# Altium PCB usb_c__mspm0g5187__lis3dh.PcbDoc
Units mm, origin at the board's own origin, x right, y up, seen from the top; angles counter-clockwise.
Board outline 92 x 60 mm, 2 copper layers (Top, Bottom), stack 0 mm thick; 34 components, 28 nets, 186 pads, 62 vias.
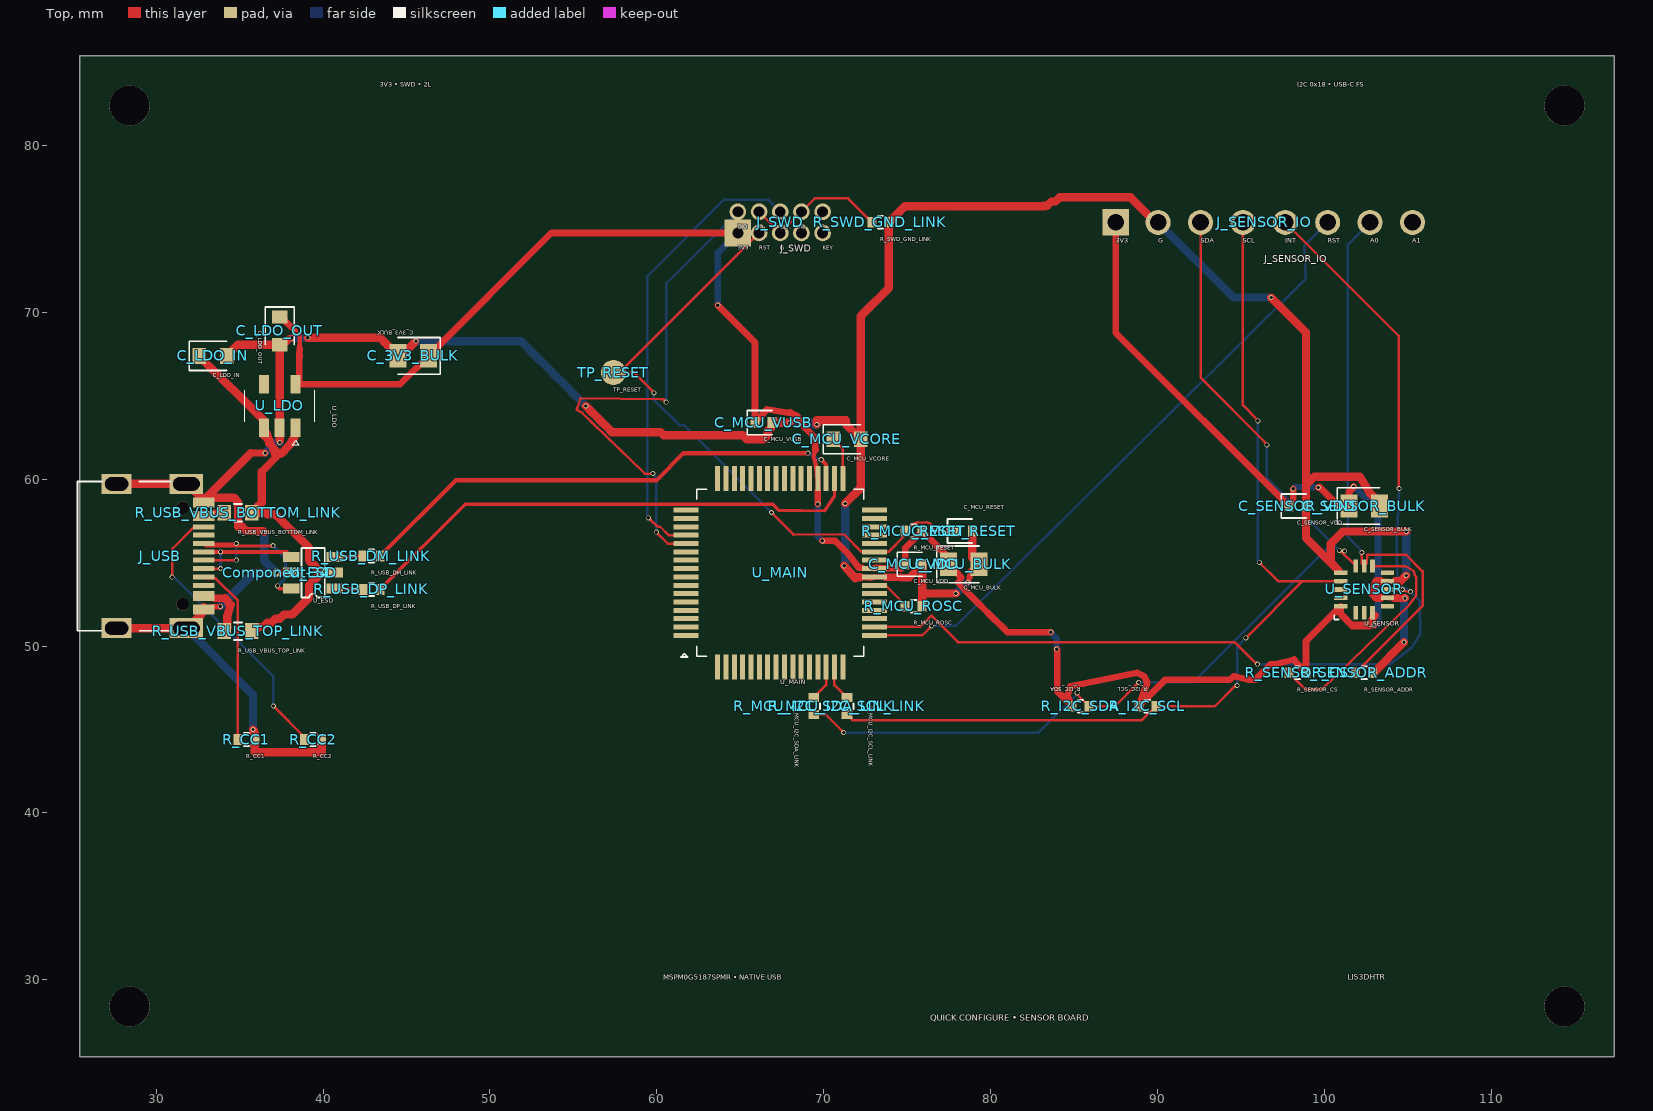
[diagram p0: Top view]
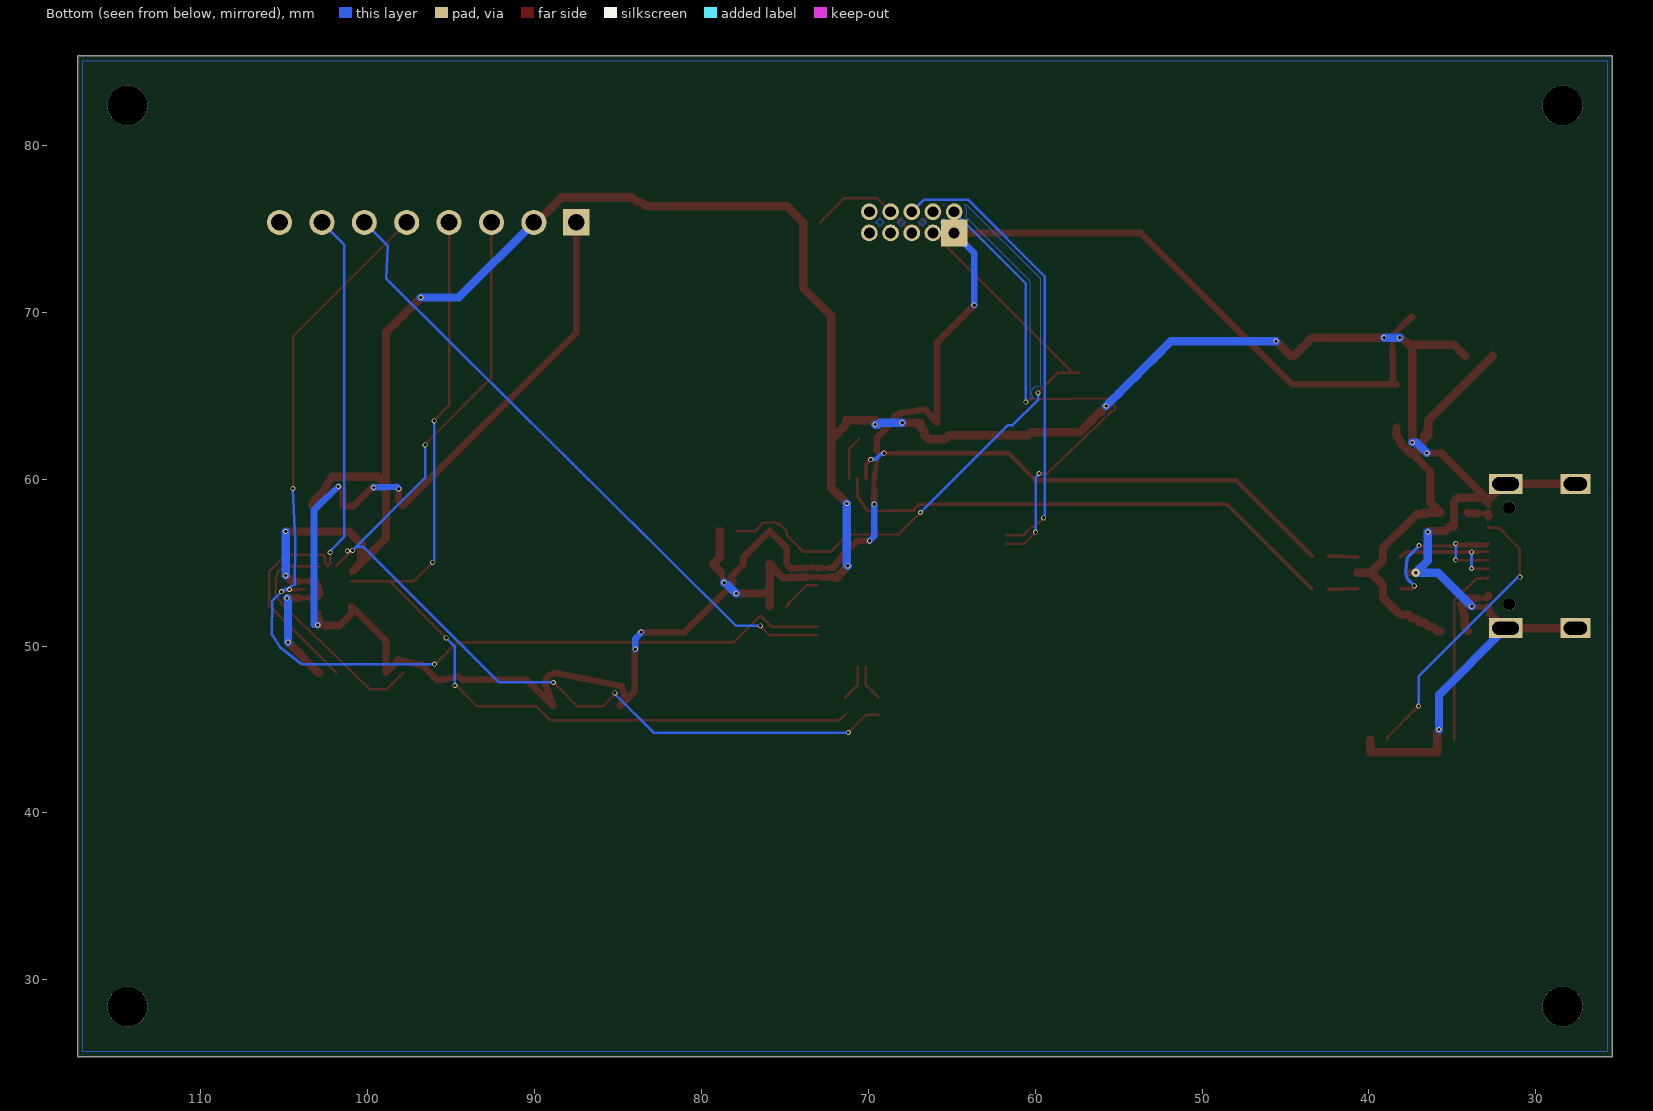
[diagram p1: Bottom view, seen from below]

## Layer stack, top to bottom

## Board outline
25.4,85.4 117.4,85.4 117.4,25.4 25.4,25.4

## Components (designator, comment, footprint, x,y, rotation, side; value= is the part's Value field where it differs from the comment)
C_3V3_BULK "" TSCIRCUIT-2.8500x1.4000mm 45.4,67.4 r180 top
C_LDO_IN "" TSCIRCUIT-2.4500x0.9500mm 33.4,67.4 r0 top
C_LDO_OUT "" TSCIRCUIT-0.9500x2.4500mm 37.4,68.9 r270 top
C_MCU_BULK "" TSCIRCUIT-2.8500x1.4000mm 78.4,54.9 r0 top
C_MCU_RESET "" TSCIRCUIT-1.5600x0.6400mm 78.4,56.9 r0 top
C_MCU_VCORE "" TSCIRCUIT-2.4500x0.9500mm 71.4,62.4 r0 top
C_MCU_VDD "" TSCIRCUIT-1.5600x0.6400mm 75.4,54.9 r0 top
C_MCU_VUSB "" TSCIRCUIT-1.5600x0.6400mm 66.4,63.4 r0 top
C_SENSOR_BULK "" TSCIRCUIT-2.8500x1.4000mm 102.4,58.4 r0 top
C_SENSOR_VDD "" TSCIRCUIT-1.5600x0.6400mm 98.4,58.4 r0 top
Component-34 "" TSCIRCUIT-0.5000x0.5000mm 37.2,54.4 r0 top
J_SENSOR_IO "" TSCIRCUIT-19.2800x1.5000mm 96.4,75.4 r0 top
J_SWD "" TSCIRCUIT-6.0800x2.2700mm 67.4,75.4 r0 top
J_USB "" TSCIRCUIT-6.7732x9.8502mm 30.113,55.4 r90 top
R_CC1 "" TSCIRCUIT-1.5600x0.6400mm 35.4,44.4 r0 top
R_CC2 "" TSCIRCUIT-1.5600x0.6400mm 39.4,44.4 r0 top
R_I2C_SCL "" TSCIRCUIT-1.5600x0.6400mm 89.4,46.4 r180 top
R_I2C_SDA "" TSCIRCUIT-1.5600x0.6400mm 85.4,46.4 r180 top
R_MCU_I2C_SCL_LINK "" TSCIRCUIT-0.6400x1.5600mm 71.4,46.4 r270 top
R_MCU_I2C_SDA_LINK "" TSCIRCUIT-0.6400x1.5600mm 69.4,46.4 r270 top
R_MCU_RESET "" TSCIRCUIT-1.5600x0.6400mm 75.4,56.9 r0 top
R_MCU_ROSC "" TSCIRCUIT-1.5600x0.6400mm 75.4,52.4 r0 top
R_SENSOR_ADDR "" TSCIRCUIT-1.5600x0.6400mm 102.4,48.4 r0 top
R_SENSOR_CS "" TSCIRCUIT-1.5600x0.6400mm 98.4,48.4 r0 top
R_SWD_GND_LINK "" TSCIRCUIT-1.5600x0.6400mm 73.4,75.4 r0 top
R_USB_DM_LINK "" TSCIRCUIT-1.5600x0.6400mm 42.9,55.4 r0 top
R_USB_DP_LINK "" TSCIRCUIT-1.5600x0.6400mm 42.9,53.4 r0 top
R_USB_VBUS_BOTTOM_LINK "" TSCIRCUIT-2.4500x0.9500mm 34.9,58 r0 top
R_USB_VBUS_TOP_LINK "" TSCIRCUIT-2.4500x0.9500mm 34.9,50.9 r0 top
TP_RESET "" TSCIRCUIT-1.5000x1.5000mm 57.4,66.4 r0 top
U_ESD "" TSCIRCUIT-3.6000x2.5000mm 39.4,54.4 r0 top
U_LDO "" TSCIRCUIT-2.5000x3.7000mm 37.4,64.4 r270 top
U_MAIN "" TSCIRCUIT-12.8000x12.8000mm 67.4,54.4 r0 top
U_SENSOR "" TSCIRCUIT-3.6001x3.5998mm 102.4,53.4 r0 top

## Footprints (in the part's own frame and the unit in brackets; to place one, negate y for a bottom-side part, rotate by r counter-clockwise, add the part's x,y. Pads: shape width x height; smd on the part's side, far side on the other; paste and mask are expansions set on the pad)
TSCIRCUIT-0.5000x0.5000mm [mm]
TSCIRCUIT-0.6400x1.5600mm [mm]
  rect 0.54x0.64 smd: 1(-0.51,0) 2(0.51,0)
  silkscreen extent -0.15,-0.38 0.15,0.38
TSCIRCUIT-0.9500x2.4500mm [mm]
  rect 0.8x0.95 smd: 1(-0.825,0) 2(0.825,0)
  silkscreen extent -1.43,-0.87 0.82,0.88
TSCIRCUIT-1.5000x1.5000mm [mm]
  round 1.5 smd: 1(0,0)
TSCIRCUIT-1.5600x0.6400mm [mm]
  rect 0.54x0.64 smd: 1(-0.51,0) 2(0.51,0)
  silkscreen extent -0.98,-0.72 0.51,0.72
TSCIRCUIT-2.4500x0.9500mm [mm]
  rect 0.8x0.95 smd: 1(-0.825,0) 2(0.825,0)
  silkscreen extent -1.42,-0.87 0.82,0.87
TSCIRCUIT-2.5000x3.7000mm [mm]
  rect 1.1x0.6 smd: 1(1.3,0.95) 2(1.3,0) 3(1.3,-0.95) 4(-1.3,-0.95) 5(-1.3,0.95)
  silkscreen extent -0.95,-2.1 2.35,2.1
TSCIRCUIT-2.8500x1.4000mm [mm]
  rect 1.025x1.4 smd: 1(-0.913,0) 2(0.913,0)
  silkscreen extent -1.63,-1.1 0.91,1.1
TSCIRCUIT-3.6000x2.5000mm [mm]
  rect 1x0.6 smd: 1(-1.3,-0.95) 2(-1.3,0) 3(-1.3,0.95) 4(1.3,0.95) 5(1.3,0) 6(1.3,-0.95)
  silkscreen extent -0.7,-1.49 0.7,1.49
TSCIRCUIT-3.6001x3.5998mm [mm]
  rect 0.8x0.28 smd: 1(-1.4,-1) 2(-1.4,-0.5) 3(-1.4,0) 4(-1.4,0.5) 5(-1.4,1) 9(1.4,1) 10(1.4,0.5) 11(1.4,0) 12(1.4,-0.5) 13(1.4,-1)
  rect 0.28x0.8 smd: 6(-0.5,1.4) 7(0,1.4) 8(0.5,1.4) 14(0.5,-1.4) 15(0,-1.4) 16(-0.5,-1.4)
  silkscreen extent -1.8,-1.8 -1.52,-1.52
TSCIRCUIT-6.0800x2.2700mm [mm]
  rect 1.6x1.6 hole 0.65: 1(-2.54,-0.635)
  round 1 hole 0.65: 2(-2.54,0.635) 3(-1.27,0.635) 4(0,0.635) 5(1.27,0.635) 6(2.54,0.635) 7(2.54,-0.635) 8(1.27,-0.635) 9(0,-0.635) 10(-1.27,-0.635)
TSCIRCUIT-6.7732x9.8502mm [mm]
  rect 0.3x1.3 smd: 1(-3.35,-2.737) 2(-3.05,-2.737) 3(-2.55,-2.737) 4(-2.25,-2.737) 5(-1.75,-2.737) 6(-1.25,-2.737) 7(-0.75,-2.737) 8(-0.25,-2.737) 9(0.25,-2.737) 10(0.75,-2.737) 11(1.25,-2.737) 12(1.75,-2.737) 13(2.55,-2.737) 14(2.25,-2.737) 15(3.35,-2.737) 16(3.05,-2.737)
  rect 1.2x2 hole 0.8 slot 1.6 at 90 deg: 17(-4.325,-1.693) 18(4.325,-1.693)
  rect 1.2x1.8 hole 0.8 slot 1.4 at 90 deg: 19(4.325,2.487) 20(-4.325,2.487)
  round 0.75 hole 0.75 unplated: NPTH-1(-2.9,-1.468) NPTH-2(2.9,-1.468)
  silkscreen extent -4.47,-0.75 4.47,4.83
TSCIRCUIT-12.8000x12.8000mm [mm]
  rect 1.5x0.3 smd: 1(-5.65,-3.75) 2(-5.65,-3.25) 3(-5.65,-2.75) 4(-5.65,-2.25) 5(-5.65,-1.75) 6(-5.65,-1.25) 7(-5.65,-0.75) 8(-5.65,-0.25) 9(-5.65,0.25) 10(-5.65,0.75) 11(-5.65,1.25) 12(-5.65,1.75) 13(-5.65,2.25) 14(-5.65,2.75) 15(-5.65,3.25) 16(-5.65,3.75) 33(5.65,3.75) 34(5.65,3.25) 35(5.65,2.75) 36(5.65,2.25) 37(5.65,1.75) 38(5.65,1.25) 39(5.65,0.75) 40(5.65,0.25) 41(5.65,-0.25) 42(5.65,-0.75) 43(5.65,-1.25) 44(5.65,-1.75) 45(5.65,-2.25) 46(5.65,-2.75) 47(5.65,-3.25) 48(5.65,-3.75)
  rect 0.3x1.5 smd: 17(-3.75,5.65) 18(-3.25,5.65) 19(-2.75,5.65) 20(-2.25,5.65) 21(-1.75,5.65) 22(-1.25,5.65) 23(-0.75,5.65) 24(-0.25,5.65) 25(0.25,5.65) 26(0.75,5.65) 27(1.25,5.65) 28(1.75,5.65) 29(2.25,5.65) 30(2.75,5.65) 31(3.25,5.65) 32(3.75,5.65) 49(3.75,-5.65) 50(3.25,-5.65) 51(2.75,-5.65) 52(2.25,-5.65) 53(1.75,-5.65) 54(1.25,-5.65) 55(0.75,-5.65) 56(0.25,-5.65) 57(-0.25,-5.65) 58(-0.75,-5.65) 59(-1.25,-5.65) 60(-1.75,-5.65) 61(-2.25,-5.65) 62(-2.75,-5.65) 63(-3.25,-5.65) 64(-3.75,-5.65)
  silkscreen extent -5.95,-5.05 5,5
TSCIRCUIT-19.2800x1.5000mm [mm]
  rect 1.6x1.6 hole 1: 1(-8.89,0)
  round 1.5 hole 1: 2(-6.35,0) 3(-3.81,0) 4(-1.27,0) 5(1.27,0) 6(3.81,0) 7(6.35,0) 8(8.89,0)

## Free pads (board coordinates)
  round 2.4 hole 2.4 unplated: NPTH-3(28.4,28.4) NPTH-4(114.4,28.4) NPTH-5(28.4,82.4) NPTH-6(114.4,82.4)

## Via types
v1: diameter 0.3, hole 0.2, Top to Bottom, 61 vias
v2: diameter 0.5, hole 0.2, Top to Bottom, 1 vias

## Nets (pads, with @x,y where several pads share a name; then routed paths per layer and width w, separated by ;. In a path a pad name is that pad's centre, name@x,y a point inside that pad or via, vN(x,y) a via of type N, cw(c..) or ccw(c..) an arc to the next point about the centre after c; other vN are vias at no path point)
".J_SWD > .pin2 to .U_MAIN > .pin12": J_SWD.2 U_MAIN.12 | length 30.9
  Top w0.15: v1(59.764,60.346) 59.277,60.346 56.137,63.368 55.527,63.99 55.2,64.175 55.425,64.85 60.238,64.787 60.405,64.787 v1(60.566,64.626) ; v1(59.968,56.831) 60.016,56.791 60.657,56.15 U_MAIN.12
  Bottom w0.15: v1(59.764,60.346) 59.801,60.301 59.801,60.266 59.97,60.097 v1(59.968,56.831) ; v1(60.566,64.626) 60.566,71.741 J_SWD.2
".J_SWD > .pin4 to .U_MAIN > .pin13": J_SWD.4 U_MAIN.13 | length 27.3
  Top w0.15: v1(59.492,57.694) 59.614,57.572 59.632,57.572 60.051,57.161 60.209,57.155 60.714,56.65 U_MAIN.13
  Bottom w0.15: v1(59.492,57.694) 59.423,57.756 59.428,72.167 64.005,76.742 66.693,76.742 J_SWD.4
".U_MAIN > .pin42 to .R_MCU_ROSC > .pin1": R_MCU_ROSC.1 U_MAIN.42 | length 2.4
  Top w0.15: U_MAIN.42 73.719,53.65 74.769,52.6 74.769,52.521 R_MCU_ROSC.1
GND: C_3V3_BULK.2 C_LDO_IN.2 C_LDO_OUT.2 C_MCU_BULK.2 C_MCU_RESET.2 C_MCU_VCORE.2 C_MCU_VDD.2 C_MCU_VUSB.2 C_SENSOR_BULK.2 C_SENSOR_VDD.2 J_SENSOR_IO.2 J_USB.1 J_USB.2 J_USB.15 J_USB.16 J_USB.17 J_USB.18 J_USB.19 J_USB.20 R_CC1.2 R_CC2.2 R_MCU_ROSC.2 R_SENSOR_ADDR.2 R_SWD_GND_LINK.2 U_ESD.2 U_LDO.2 U_MAIN.41 U_SENSOR.5 U_SENSOR.10 U_SENSOR.12 | length 203.3
  Top w0.275: J_USB.16 J_USB.15@33.04,58.641
  Top w0.28: U_SENSOR.12@103.4,52.9 U_SENSOR.12 ; U_SENSOR.10@103.4,53.9 U_SENSOR.10 103.894,53.9 103.988,53.9 104.081,53.9 104.175,53.9 104.2,53.9 104.269,53.9 ; U_SENSOR.5@100.86,54.54 U_SENSOR.5 U_SENSOR.5@100.86,54.54
  Top w0.287: U_SENSOR.12 103.817,52.883 104.159,52.88 U_SENSOR.12@104.2,52.88
  Top w0.3: J_USB.1@32.699,51.9 J_USB.1 J_USB.1@32.849,52.2 ; J_USB.15@32.699,58.9 J_USB.15 ; J_USB.16@32.849,58.6 J_USB.15 ; J_USB.15@32.999,58.9 J_USB.15 ; J_USB.15@33.04,58.641 33.231,58.832 33.332,58.832 33.4,58.9 33.499,58.9 ; U_MAIN.41 73.144,54.15 73.237,54.15 73.331,54.15 73.425,54.15 73.519,54.15 73.612,54.15 U_MAIN.41@73.706,54.15
  Top w0.325: J_USB.2 J_USB.2@32.887,52.324 ; J_USB.16 J_USB.16@32.849,58.6 ; v1(37.395,62.205) v1@37.4,62.35 ; v1(78.645,53.806) 78.741,54.116
  Top w0.33: U_MAIN.41@72.425,54.117 72.55,54.114 U_MAIN.41@72.675,54.112
  Top w0.331: U_MAIN.41@72.675,54.112 U_MAIN.41@72.796,54.101
  Top w0.335: 72.3,54.12 U_MAIN.41@72.425,54.117
  Top w0.35: J_USB.2@32.887,52.324 33.362,52.354 v1(33.836,52.384) ; 37.968,68.441 38.124,68.441 v1(38.153,68.477)
  Top w0.375: 45.429,68.145 45.435,68.145 v1(45.568,68.278) ; U_MAIN.41@72.796,54.101 U_MAIN.41 ; 78.741,54.116 C_MCU_BULK.2@78.838,54.425
  Top w0.4: 35.673,61.574 36.1,61.574 v1(36.527,61.574) ; 37.2,54.4 U_ESD.2@37.6,54.4 ; 72.175,54.12 72.3,54.12
  Top w0.425: C_LDO_OUT.2@37.785,68.258 37.968,68.441
  Top w0.437: 75.119,54.087 75.337,54.306 75.556,54.525
  Top w0.45: 74.648,54.108 75.119,54.087
  Top w0.475: U_MAIN.41@73.706,54.15 74.177,54.129 74.648,54.108 ; 104.2,52.88 104.501,52.877 v1(104.844,52.874)
  Top w0.5: J_USB.20 J_USB.17 31.874,51.075 32.474,51.675 32.699,51.9 ; J_USB.19 J_USB.18 31.874,59.725 32.474,59.125 32.699,58.9 ; J_USB.1@32.849,52.2 J_USB.2 ; 32.999,58.9 35.673,61.574 ; 33.499,58.9 34.65,58.9 34.9,58.65 34.9,57.15 35.15,57.15 35.4,56.9 36.409,56.9 v1(36.463,56.846) ; C_LDO_IN.2 34.9,68.075 C_LDO_OUT.2 ; v1(35.8,45) 35.838,44.962 35.838,44.87 35.91,44.798 R_CC1.2 35.91,43.65 39.91,43.65 R_CC2.2 ; v1@37.4,62.35 37.4,62.725 U_LDO.2 C_LDO_OUT.2 ; C_LDO_OUT.2@37.785,68.258 37.603,68.075 C_LDO_OUT.2 ; v1(39.081,68.491) 39.56,68.491 40.04,68.491 40.519,68.491 40.999,68.491 41.478,68.491 41.958,68.491 42.437,68.491 42.917,68.491 43.396,68.491 43.669,68.218 43.942,67.946 44.215,67.673 C_3V3_BULK.2 44.683,67.4 44.932,67.648 45.18,67.897 45.429,68.145 ; v1(55.747,64.394) 56.062,64.079 56.376,63.765 56.691,63.45 57.005,63.136 57.32,62.821 57.794,62.821 58.268,62.821 58.743,62.821 59.217,62.821 59.691,62.821 60.166,62.821 60.229,62.821 60.4,62.65 65.15,62.65 65.4,62.4 66.4,62.4 66.65,62.65 66.65,62.9 66.9,63.15 66.9,63.4 C_MCU_VUSB.2 67.91,63.4 v1(67.97,63.39) ; v1(69.589,63.289) 69.589,63.539 71.336,63.539 71.336,63.289 C_MCU_VCORE.2 ; v1(71.229,54.813) 71.898,54.077 72.05,54.12 72.175,54.12 ; v1(71.292,58.547) 72.225,59.48 C_MCU_VCORE.2 ; 75.556,54.525 75.66,54.65 C_MCU_VDD.2 ; R_MCU_ROSC.2 C_MCU_VDD.2 ; v1(77.92,53.159) 75.91,53.159 C_MCU_VDD.2 ; C_MCU_BULK.2@78.838,54.425 79.075,54.662 C_MCU_BULK.2 78.91,55.303 C_MCU_RESET.2 ; J_SENSOR_IO.2 89.9,75.4 88.4,76.9 84.15,76.9 83.9,76.65 83.65,76.65 83.4,76.4 83.202,76.4 83.235,76.366 82.748,76.366 82.261,76.366 81.773,76.366 81.286,76.366 80.799,76.366 80.311,76.366 79.824,76.366 79.337,76.366 78.849,76.366 78.362,76.366 77.875,76.366 77.387,76.366 76.9,76.366 76.413,76.366 75.925,76.366 75.438,76.366 74.951,76.366 74.876,76.366 74.554,76.044 74.232,75.722 R_SWD_GND_LINK.2 73.91,71.464 72.225,69.779 72.225,69.287 72.225,68.795 72.225,68.303 72.225,67.812 72.225,67.32 72.225,66.828 72.225,66.336 72.225,65.844 72.225,65.352 72.225,64.86 72.225,64.368 72.225,63.876 72.225,63.384 72.225,62.892 C_MCU_VCORE.2 ; v1(96.819,70.897) 98.91,68.806 C_SENSOR_VDD.2 ; R_SENSOR_ADDR.2 102.947,48.4 v1(104.788,50.24) ; C_SENSOR_BULK.2 103.318,58.573 103.029,58.873 102.74,59.173 102.15,60.15 99.4,60.15 98.91,59.66 C_SENSOR_VDD.2 ; U_SENSOR.12@103.4,52.9 103.15,52.9 102.9,53.15 103.15,53.9 U_SENSOR.10@103.4,53.9 ; 104.269,53.9 104.363,53.9 104.456,53.9 104.55,53.9 104.579,53.9 104.912,54.233 v1(104.915,54.236) ; v1(104.925,56.871) 101.121,56.871 100.4,56.15 100.4,55 100.86,54.54 98.91,56.49 C_SENSOR_VDD.2
  Bottom w0.5: J_USB.17 35.8,47.081 v1(35.8,45) ; v1(33.836,52.384) 35.853,54.4 37.2,54.4 36.954,54.646 36.709,54.891 36.463,55.137 36.463,55.564 36.463,55.992 36.463,56.419 v1(36.463,56.846) ; v1(36.527,61.574) 37.158,62.205 v1(37.395,62.205) ; v1(38.153,68.477) 39.067,68.477 v1(39.081,68.491) ; v1(45.568,68.278) 46.052,68.278 46.536,68.278 47.021,68.278 47.505,68.278 47.989,68.278 48.473,68.278 48.958,68.278 49.442,68.278 49.926,68.278 50.41,68.278 50.895,68.278 51.379,68.278 51.863,68.278 52.214,67.927 52.564,67.577 52.915,67.226 53.265,66.876 53.616,66.525 53.966,66.175 54.317,65.824 54.667,65.474 55.018,65.123 55.368,64.773 55.719,64.422 v1(55.747,64.394) ; v1(67.97,63.39) 69.286,63.4 69.422,63.263 69.563,63.263 v1(69.589,63.289) ; v1(71.229,54.813) 71.292,54.876 v1(71.292,58.547) ; v1(77.92,53.159) 77.939,53.159 78.197,53.417 78.455,53.675 78.475,53.675 v1(78.645,53.806) ; J_SENSOR_IO.2 94.553,70.897 v1(96.819,70.897) ; v1(104.788,50.24) 104.788,52.818 v1(104.844,52.874) ; v1(104.915,54.236) 104.915,56.861 v1(104.925,56.871)
MAIN_RESET: C_MCU_RESET.1 J_SWD.10 R_MCU_RESET.1 TP_RESET.1 U_MAIN.38 | length 38.6
  Top w0.15: v1(59.83,65.183) 59.715,65.298 59.715,65.315 58.629,66.4 TP_RESET.1 57.765,66.4 J_SWD.10 ; v1(66.872,58.008) 68.193,56.687 70.959,56.71 71.235,56.687 72.273,55.65 U_MAIN.38 73.889,55.65 74.889,56.651 R_MCU_RESET.1@74.889,56.899 ; R_MCU_RESET.1 75.256,57.266 75.34,57.266 75.254,57.273 75.637,57.423 75.9,57.41 76.161,57.425 76.332,57.372 76.764,56.9 C_MCU_RESET.1
  Bottom w0.15: v1(59.83,65.183) 59.83,64.765 61.351,63.244 61.636,63.244 66.85,58.03 v1(66.872,58.008)
MCU_I2C_SCL_LOCAL: R_MCU_I2C_SCL_LINK.1 U_MAIN.50 | length 2.2
  Top w0.15: U_MAIN.50 70.65,47.66 R_MCU_I2C_SCL_LINK.1
MCU_I2C_SDA_LOCAL: R_MCU_I2C_SDA_LINK.1 U_MAIN.51 | length 2.2
  Top w0.15: R_MCU_I2C_SDA_LINK.1 70.15,47.66 U_MAIN.51
MSPM0_VCORE: C_MCU_VCORE.1 U_MAIN.32 | length 2.6
  Top w0.15: C_MCU_VCORE.1 71.15,61.825 U_MAIN.32
SENSOR_ADDR0: J_SENSOR_IO.7 R_SENSOR_ADDR.1 U_SENSOR.7 | length 33.8
  Top w0.15: R_SENSOR_ADDR.1 105.906,52.416 105.906,54.486 104.917,55.476 102.577,55.476 102.564,54.982 U_SENSOR.7 102.254,54.946 v1(102.254,55.615)
  Bottom w0.15: v1(102.254,55.615) 102.194,55.675 102.194,55.775 101.417,56.552 101.417,56.703 101.417,74.067 J_SENSOR_IO.7
SENSOR_ADDR1: J_SENSOR_IO.8
SENSOR_CS: R_SENSOR_CS.1 U_SENSOR.8 | length 14.4
  Top w0.15: R_SENSOR_CS.1 98.885,47.405 99.859,47.404 105.103,52.473 105.524,53.055 105.515,54.154 105.421,54.247 105.375,54.5 104.869,54.8 U_SENSOR.8
SENSOR_INT: J_SENSOR_IO.5 U_MAIN.47 U_SENSOR.11 | length 66
  Top w0.15: U_MAIN.47 75.785,51.15 76.46,51.825 78.046,50.238 94.621,50.238 94.631,50.238 95.861,49.009 95.915,49.009 v1(96.005,48.919) ; J_SENSOR_IO.5 104.471,68.599 104.471,59.467 104.475,59.467 v1(104.497,59.445) ; v1(104.7,53.4) U_SENSOR.11 v1(105.179,53.265)
  Bottom w0.15: v1(96.005,48.919) 103.957,48.914 105.235,49.903 105.745,50.698 105.738,52.706 105.22,53.224 v1(105.179,53.265) ; v1(104.497,59.445) 104.365,56.306 104.368,53.673 105.205,53.315 105.205,53.291 v1(104.7,53.4)
SENSOR_RESET: J_SENSOR_IO.6 U_MAIN.48 | length 38.6
  Top w0.15: U_MAIN.48 75.912,50.65 76.363,51.101 76.363,51.109 v1(76.476,51.222)
  Bottom w0.15: v1(76.476,51.222) 77.919,51.214 98.889,72.017 98.798,73.988 J_SENSOR_IO.6
SENSOR_SCL: J_SENSOR_IO.4 R_I2C_SCL.1 R_MCU_I2C_SCL_LINK.2 U_SENSOR.4 | length 60.7
  Top w0.15: R_MCU_I2C_SCL_LINK.2 71.719,45.571 89.004,45.571 89.081,45.571 R_I2C_SCL.1 93.449,46.4 94.659,47.61 94.745,47.61 v1(94.781,47.646) ; J_SENSOR_IO.4 95.13,64.445 96.045,63.529 96.045,63.525 v1(96.02,63.5) ; v1(95.31,50.501) 98.709,53.9 U_SENSOR.4 97.234,53.9 v1(96.11,55.024)
  Bottom w0.15: v1(94.781,47.646) 94.781,49.962 95.264,50.444 95.264,50.455 v1(95.31,50.501) ; v1(96.02,63.5) 96.02,55.126 96.108,55.038 96.108,55.026 v1(96.11,55.024)
SENSOR_SDA: J_SENSOR_IO.3 R_I2C_SDA.1 R_MCU_I2C_SDA_LINK.2 U_SENSOR.6 | length 63.9
  Top w0.15: R_MCU_I2C_SDA_LINK.2 70.13,45.89 71.028,44.992 v1(71.2,44.82) ; v1(85.2,47.2) 85.2,47.11 R_I2C_SDA.1 87.457,46.4 88.818,47.761 v1(88.882,47.825) ; J_SENSOR_IO.3 92.59,66.096 96.441,62.245 96.441,62.184 v1(96.56,62.065) ; v1(100.914,55.745) v1@100.955,55.745 ; v1(101.225,55.7) v1@100.955,55.745 ; v1@100.955,55.745 U_SENSOR.6 v1@100.955,55.745
  Bottom w0.15: v1(71.2,44.82) 82.879,44.82 85.2,47.141 v1(85.2,47.2) ; v1(88.882,47.825) 92.146,47.825 100.267,55.946 100.665,55.946 100.913,55.698 100.913,55.744 v1(101.225,55.7) ; v1(96.56,62.065) 96.56,60.1 v1@100.831,55.829 ; v1@100.831,55.828 v1(100.914,55.745)
swd-ground-1-to-2: J_SWD.3 J_SWD.5 J_SWD.9 R_SWD_GND_LINK.1 | length 8.8
  Top w0.15: J_SWD.3 J_SWD.9 J_SWD.5 69.481,76.846 71.471,76.846 71.471,76.819 R_SWD_GND_LINK.1
usb-dm-device: R_USB_DM_LINK.1 U_ESD.4 | length 1.7
  Top w0.25: U_ESD.4 R_USB_DM_LINK.1
usb-dm-mcu: R_USB_DM_LINK.2 U_MAIN.30 | length 30.4
  Top w0.25: R_USB_DM_LINK.2 47.95,59.94 59.983,59.94 61.609,61.566 v1(69.057,61.566) ; v1(69.857,61.178) 70.15,60.885 U_MAIN.30
  Bottom w0.25: v1(69.057,61.566) 69.107,61.516 69.248,61.516 69.585,61.178 v1(69.857,61.178)
usb-dm-port-tie: J_USB.7 J_USB.9 U_ESD.3 | length 8.4
  Top w0.15: J_USB.7 v1(33.85,54.65) ; J_USB.9@33.35,55.65 33.318,55.65 33.224,55.65 33.13,55.65 33.037,55.65 32.943,55.65 J_USB.9 v1(33.85,55.65)
  Top w0.175: J_USB.9@33.35,55.65 J_USB.9@33.412,55.65
  Top w0.212: J_USB.9@33.412,55.65 33.505,55.65
  Top w0.25: 33.505,55.65 33.599,55.645 37.8,55.631 U_ESD.3
  Bottom w0.15: v1(33.85,54.65) v1(33.85,55.65)
usb-dp-device: R_USB_DP_LINK.1 U_ESD.6 | length 1.7
  Top w0.25: U_ESD.6 R_USB_DP_LINK.1
usb-dp-mcu: R_USB_DP_LINK.2 U_MAIN.31 | length 31
  Top w0.2: R_USB_DP_LINK.2 48.512,58.502 48.527,58.502 66.966,58.502 67.008,58.46 67.319,58.148 70.05,58.1 70.65,58.99 U_MAIN.31
usb-dp-port-tie: J_USB.8 J_USB.10 U_ESD.1 | length 12.9
  Top w0.15: J_USB.8 v1(34.8,55.15) ; J_USB.10 v1(34.8,56.15)
  Top w0.2: J_USB.10 32.999,56 v1(37,56.024) ; v1(37.275,53.615) 37.358,53.532 37.358,53.47 37.379,53.45 U_ESD.1
  Bottom w0.15: v1(34.8,55.15) v1(34.8,56.15)
  Bottom w0.2: v1(37,56.024) 37.079,55.921 37.71,55.289 37.71,55.183 37.8,54.5 37.71,54.05 v1(37.275,53.615)
USB_CC1: J_USB.6 R_CC1.1 | length 11
  Top w0.15: J_USB.6 32.937,54.062 33.562,54.062 34.89,52.734 R_CC1.1
USB_CC2: J_USB.12 R_CC2.1 | length 17.2
  Top w0.15: v1(30.956,54.138) 30.956,55.826 32.236,57.106 32.805,57.106 J_USB.12 ; v1(37.019,46.41) 37.075,46.354 38.89,44.539 R_CC2.1
  Bottom w0.15: v1(30.956,54.138) 31.061,54.138 37.019,48.18 v1(37.019,46.41)
USB_VBUS_BOTTOM_LOCAL: J_USB.13 J_USB.14 R_USB_VBUS_BOTTOM_LINK.1 | length 1.5
  Top w0.3: J_USB.14 J_USB.14@32.849,57.8 ; J_USB.13 32.927,57.95 33.005,57.95 33.083,57.95 33.161,57.95 33.239,57.95 33.317,57.95 33.394,57.95 33.472,57.95 33.499,57.95
  Top w0.475: J_USB.13@32.849,57.8 J_USB.13 ; 33.499,57.95 R_USB_VBUS_BOTTOM_LINK.1@33.762,57.95
  Top w0.5: R_USB_VBUS_BOTTOM_LINK.1@33.762,57.95 34.025,57.95 R_USB_VBUS_BOTTOM_LINK.1
USB_VBUS_TOP_LOCAL: J_USB.3 J_USB.4 R_USB_VBUS_TOP_LINK.1 | length 3.8
  Top w0.3: J_USB.4 32.849,53 J_USB.3 J_USB.3@32.946,52.868 ; J_USB.3@33.13,52.85 33.165,52.884 33.228,52.884 33.499,52.884
  Top w0.301: J_USB.3@32.946,52.868 33.037,52.85 J_USB.3@33.13,52.85
  Top w0.45: 33.499,52.884 33.666,52.884 34.103,52.884
  Top w0.5: R_USB_VBUS_TOP_LINK.1 34.245,51.064 34.254,51.443 34.263,51.823 34.363,52.158 34.462,52.494 34.275,52.681 34.103,52.884
VBUS5: C_LDO_IN.1 R_USB_VBUS_BOTTOM_LINK.2 R_USB_VBUS_TOP_LINK.2 U_ESD.5 U_LDO.1 U_LDO.3 | length 29.6
  Top w0.437: 36.781,62.342 36.947,61.962 37.056,61.634 37.166,61.306
  Top w0.45: 36.315,60.455 37.166,61.306 ; 36.761,62.148 37.384,61.525 37.466,61.525
  Top w0.5: C_LDO_IN.1 36.45,63.525 U_LDO.3 ; R_USB_VBUS_TOP_LINK.2 35.9,50.9 36.15,51.15 36.4,51.15 36.65,51.4 36.9,51.4 37.15,51.65 37.4,51.65 37.65,51.9 38.15,51.9 39.15,52.9 39.15,53.65 39.9,54.4 ; 36.315,60.455 36.315,58.59 36.02,58.295 R_USB_VBUS_BOTTOM_LINK.2 36.225,58 36.725,58 36.65,57.925 36.65,57.9 37.15,57.9 39.15,55.9 39.15,55.15 39.9,54.4 ; 36.761,62.148 36.761,62.336 36.45,62.647 U_LDO.3 ; 36.781,62.342 36.616,62.721 U_LDO.3 ; 37.466,61.525 37.998,62.057 38.175,62.371 38.351,62.684 U_LDO.1 ; 39.9,54.4 U_ESD.5 39.9,54.4
VCC_3V3: C_3V3_BULK.1 C_LDO_OUT.1 C_MCU_BULK.1 C_MCU_VDD.1 C_MCU_VUSB.1 C_SENSOR_BULK.1 C_SENSOR_VDD.1 J_SENSOR_IO.1 J_SWD.1 R_I2C_SCL.2 R_I2C_SDA.2 R_MCU_RESET.2 R_SENSOR_CS.2 U_LDO.5 U_MAIN.29 U_MAIN.40 U_SENSOR.1 U_SENSOR.14 | length 151.5
  Top w0.25: 69.525,60.9 69.463,61.15 69.4,61.4 69.525,61.775
  Top w0.262: 69.525,60.9 69.567,60.617 U_MAIN.29@69.608,60.333
  Top w0.275: 38.309,68.903 38.594,68.628 38.59,68.241 38.587,67.854
  Top w0.28: U_SENSOR.1@100.86,52.26 U_SENSOR.1 U_SENSOR.1@101,52.26 ; U_SENSOR.14 U_SENSOR.14@103.04,51.86
  Top w0.3: U_MAIN.29@69.65,59.321 69.65,59.686 U_MAIN.29 ; 72.3,54.689 U_MAIN.40
  Top w0.325: U_MAIN.29@69.608,60.333 U_MAIN.29
  Top w0.35: 38.025,69.178 38.309,68.903 ; 78.225,54.05 78.05,53.825 78.225,53.6 78.37,53.455
  Top w0.357: U_MAIN.40@72.72,54.684 73.087,54.714 73.43,54.701 U_MAIN.40@73.773,54.688
  Top w0.363: U_MAIN.40@72.72,54.684 U_MAIN.40 ; 78.37,53.455 78.516,53.311
  Top w0.387: 38.583,67.467 38.587,67.854
  Top w0.4: C_LDO_OUT.1 37.456,69.728 37.74,69.453 38.025,69.178 ; 38.583,67.467 38.58,67.08 38.576,66.693 38.572,66.306 38.569,65.919 U_LDO.5 44.613,65.7 C_3V3_BULK.1 53.678,74.765 J_SWD.1 ; v1(63.655,70.439) 63.674,70.42 65.89,68.204 C_MCU_VUSB.1 66.17,63.68 66.6,64.2 68.016,63.969 68,64 68.4,63.8 68.752,63.226 68.997,62.979 69.243,62.731 69.488,62.484 69.488,62.105 69.489,61.727 69.525,61.775 ; v1(69.648,58.507) 69.642,58.508 69.642,58.585 69.65,58.593 69.65,58.957 U_MAIN.29@69.65,59.321 ; v1(69.922,56.313) 70.302,56.313 70.682,56.313 70.946,56.049 71.209,55.786 71.473,55.522 72.1,54.7 72.3,54.689 ; U_MAIN.40@73.773,54.688 74.116,54.675 73.801,54.685 74.64,54.65 C_MCU_VDD.1 74.89,55.88 R_MCU_RESET.2 77.488,55.323 C_MCU_BULK.1 77.742,54.641 77.996,54.381 78.25,54.122 78.225,54.05 ; 78.516,53.311 78.795,53.036 79.073,52.761 79.352,52.485 79.63,52.21 79.909,51.935 80.188,51.66 80.466,51.385 80.745,51.11 81.023,50.835 81.395,50.835 81.766,50.835 82.137,50.835 82.508,50.835 82.88,50.835 83.251,50.835 v1(83.622,50.835) ; v1(83.966,49.821) 84.004,49.783 84.004,49.426 84.004,49.069 84.004,48.713 84.004,48.356 84.004,47.999 84.004,47.642 84.004,47.286 84.226,47.064 84.447,46.843 84.669,46.621 R_I2C_SDA.2 84.6,47 84.8,47.6 88.8,48.4 89.2,48.2 89.4,47.8 R_I2C_SCL.2 89.155,46.665 89.42,46.93 89.685,47.195 89.95,47.46 90.215,47.725 90.48,47.99 90.865,47.99 91.25,47.99 91.634,47.99 92.019,47.99 92.404,47.99 92.788,47.99 93.173,47.99 93.558,47.99 93.942,47.99 94.327,47.99 94.6,48.2 95.481,47.99 95.865,47.99 96.092,48.22 96.318,48.449 96.544,48.678 96.77,48.907 97.099,48.908 98.2,49.2 98.662,48.656 R_SENSOR_CS.2 98.91,50.31 U_SENSOR.1@100.86,52.26 ; J_SENSOR_IO.1 87.51,68.78 C_SENSOR_VDD.1 98.146,58.656 v1(98.146,59.434) ; v1(99.65,59.506) 99.718,59.548 100.865,58.4 C_SENSOR_BULK.1 101.488,58.68 101.488,58.961 101.488,59.241 101.632,59.385 101.777,59.53 101.771,59.571 v1(101.767,59.567) ; 101,52.26 101,52.167 101,51.933 101.269,51.664 101.7,51.2 102.7,51.2 102.9,51.6 102.866,51.626 103.096,51.856 103.044,51.856 U_SENSOR.14@103.04,51.86 ; U_SENSOR.1 101.001,52.399 101.001,52.151 101.001,51.903 101.213,51.692 101.424,51.48 101.636,51.269 101.977,51.269 102.319,51.269 102.66,51.269 v1(103.002,51.269)
  Bottom w0.35: v1(101.767,59.567) 102.01,59.335 102.253,59.103
  Bottom w0.4: v1(63.655,70.439) 63.655,73.56 J_SWD.1 ; v1(69.648,58.507) 69.649,58.123 69.649,57.738 69.649,57.354 69.65,56.969 69.65,56.585 69.885,56.35 v1(69.922,56.313) ; v1(83.622,50.835) 83.705,50.752 83.705,50.712 83.966,50.45 83.966,50.136 v1(83.966,49.821) ; v1(98.146,59.434) 98.153,59.441 98.262,59.55 v1(99.65,59.506) ; 102.253,59.103 102.497,58.871 102.74,58.638 102.983,58.406 103.226,58.174 103.226,57.791 103.226,57.409 103.226,57.026 103.226,56.644 103.226,56.261 103.226,55.879 103.226,55.496 103.226,55.113 103.226,54.731 103.226,54.348 103.226,53.966 103.226,53.583 103.226,53.201 103.226,52.818 103.226,52.436 103.226,52.053 103.226,51.671 103.226,51.288 103.021,51.288 v1(103.002,51.269)
pads on no net: J_SWD.6 J_SWD.7 J_SWD.8 J_USB.5 J_USB.11 J_USB.NPTH-1 J_USB.NPTH-2 U_LDO.4 U_MAIN.1 U_MAIN.2 U_MAIN.3 U_MAIN.4 U_MAIN.5 U_MAIN.6 U_MAIN.7 U_MAIN.8 U_MAIN.9 U_MAIN.10 U_MAIN.11 U_MAIN.14 U_MAIN.15 U_MAIN.16 U_MAIN.17 U_MAIN.18 U_MAIN.19 U_MAIN.20 U_MAIN.21 U_MAIN.22 U_MAIN.23 U_MAIN.24 U_MAIN.25 U_MAIN.26 U_MAIN.27 U_MAIN.28 U_MAIN.33 U_MAIN.34 U_MAIN.35 U_MAIN.36 U_MAIN.37 U_MAIN.39 U_MAIN.43 U_MAIN.44 U_MAIN.45 U_MAIN.46 U_MAIN.49 U_MAIN.52 U_MAIN.53 U_MAIN.54 U_MAIN.55 U_MAIN.56 U_MAIN.57 U_MAIN.58 U_MAIN.59 U_MAIN.60 U_MAIN.61 U_MAIN.62 U_MAIN.63 U_MAIN.64 U_SENSOR.2 U_SENSOR.3 U_SENSOR.9 U_SENSOR.13 U_SENSOR.15 U_SENSOR.16
copper on no net:
  other v2: 37.2,54.4

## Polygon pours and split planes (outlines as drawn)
GND on Bottom (solid): 117.1,85.1 25.7,85.1 25.7,25.7 117.1,25.7
GND on Bottom (solid): 65.519,76.467 65.471,76.467 65.484,76.452 65.495,76.43 65.506,76.452
GND on Bottom (solid): 65.495,75.64 65.484,75.618 65.399,75.515 65.591,75.515 65.506,75.618
GND on Bottom (solid): 65.61,75.496 65.61,75.304 65.713,75.389 65.735,75.4 65.713,75.411
GND on Bottom (solid): 69.305,75.64 69.294,75.618 69.2,75.505 69.087,75.411 69.065,75.4 69.087,75.389 69.2,75.295 69.294,75.182 69.305,75.16 69.316,75.182 69.41,75.295 69.523,75.389 69.545,75.4 69.523,75.411 69.41,75.505 69.316,75.618
GND on Bottom (solid): 68.035,75.64 68.024,75.618 67.93,75.505 67.817,75.411 67.795,75.4 67.817,75.389 67.93,75.295 68.024,75.182 68.035,75.16 68.046,75.182 68.14,75.295 68.253,75.389 68.275,75.4 68.253,75.411 68.14,75.505 68.046,75.618
GND on Bottom (solid): 66.765,75.64 66.754,75.618 66.66,75.505 66.547,75.411 66.525,75.4 66.547,75.389 66.66,75.295 66.754,75.182 66.765,75.16 66.776,75.182 66.87,75.295 66.983,75.389 67.005,75.4 66.983,75.411 66.87,75.505 66.776,75.618
GND on Bottom (solid): 64.249,76.467 64.119,76.467 59.703,72.053 59.701,65.56 59.752,65.575 59.83,65.583 59.908,65.575 59.983,65.553 60.052,65.516 60.113,65.466 60.163,65.405 60.2,65.336 60.222,65.261 60.23,65.183 60.222,65.105 60.2,65.03 60.163,64.961 60.113,64.9 60.105,64.894 60.105,64.878 60.199,64.784 60.233,64.848 60.283,64.909 60.291,64.915 60.291,71.741 60.296,71.795 60.312,71.846 60.337,71.894 60.372,71.935 64.173,75.737 64.167,75.748 64.124,75.889 64.11,76.035 64.124,76.181 64.167,76.322 64.236,76.452

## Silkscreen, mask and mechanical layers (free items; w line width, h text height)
Top Overlay:
  text "3V3 • SWD • 2L" at 43.4,83.4 h0.48
  text "I2C 0x18 • USB-C FS" at 98.4,83.4 h0.5
  text "MSPM0G5187SPMR • NATIVE USB" at 60.4,29.9 h0.52
  text "LIS3DHTR" at 101.4,29.9 h0.55
  text "QUICK CONFIGURE • SENSOR BOARD" at 76.4,27.4 h0.65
